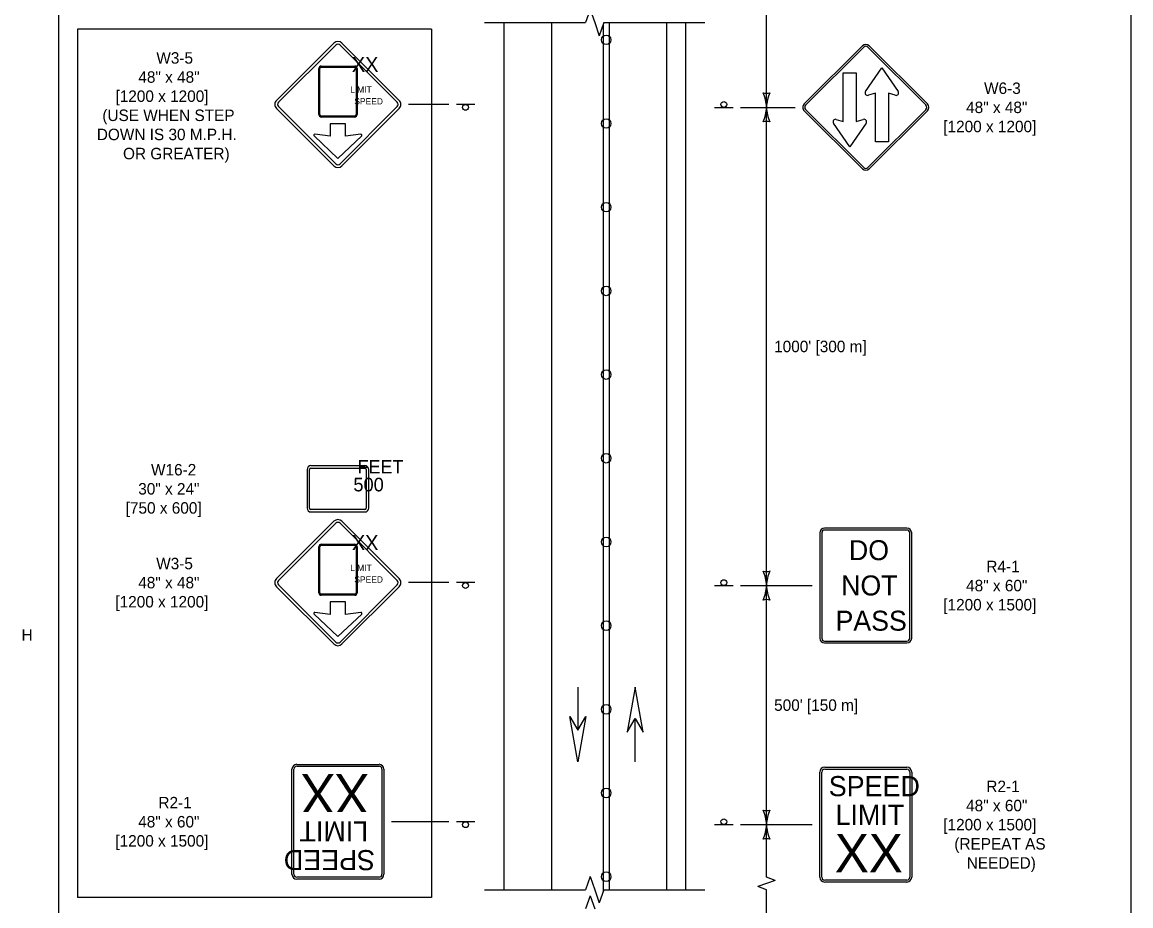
# Model space of a CAD drawing. Extents: x 49991.4 to 50021, y 49987.6 to 50011.4.
# Drawn here: x 50010.96 to 50016.75, y 49990.69 to 49995.31 of the extents above; entities that cross this region are included whole.
import ezdxf

# ---------------------------------------------------------------- set-up
doc = ezdxf.new("R2010")
doc.units = 0
for name, color, linetype in [('Level 1', 7, 'Continuous'), ('Level 2', 7, 'Continuous'), ('Level 3', 7, 'Continuous'), ('Level 6', 7, 'Continuous')]:
    doc.layers.add(name, color=color, linetype=linetype)

msp = doc.modelspace()

# ---------------------------------------------------------------- linework, layer by layer
at = {"layer": 'Level 1'}
for p, q in [((50013.4728, 49995.3125), (50013.4728, 49990.779)), ((50013.7228, 49995.3125), (50013.7228, 49990.779)), ((50013.9928, 49995.3023), (50013.9928, 49990.7689)), ((50014.0228, 49995.3125), (50014.0228, 49990.779)), ((50014.3228, 49995.3125), (50014.3228, 49990.779)), ((50014.4228, 49995.3125), (50014.4228, 49990.779)), ((50012.5844, 49995.2049), (50012.2851, 49994.9056)), ((50012.9264, 49994.9056), (50012.6271, 49995.2049)), ((50012.5945, 49995.1948), (50012.2952, 49994.8955)), ((50012.9163, 49994.8955), (50012.617, 49995.1948)), ((50015.0432, 49994.8868), (50015.3472, 49995.1908)), ((50015.0504, 49994.8798), (50015.3544, 49995.1838)), ((50015.3756, 49995.1838), (50015.6796, 49994.8798)), ((50015.3826, 49995.1908), (50015.6868, 49994.8868)), ((50012.5189, 49995.0848), (50012.6936, 49995.0848)), ((50012.5064, 49994.831), (50012.5064, 49995.0723)), ((50012.5116, 49994.831), (50012.5116, 49995.0723)), ((50012.5189, 49995.0796), (50012.6936, 49995.0796)), ((50012.7009, 49995.0723), (50012.7009, 49994.831)), ((50012.7061, 49995.0723), (50012.7061, 49994.831)), ((50015.2472, 49994.7942), (50015.2472, 49995.0498)), ((50015.2472, 49995.0498), (50015.3152, 49995.0498)), ((50015.3152, 49995.0498), (50015.3152, 49994.7942)), ((50015.3636, 49994.9518), (50015.4488, 49995.0754)), ((50015.4488, 49995.0754), (50015.5338, 49994.9518)), ((50015.4148, 49994.9438), (50015.3784, 49994.9322)), ((50015.4148, 49994.6884), (50015.4148, 49994.9438)), ((50015.5192, 49994.9322), (50015.4828, 49994.9438)), ((50015.4828, 49994.9438), (50015.4828, 49994.6884)), ((50012.2851, 49994.8629), (50012.5844, 49994.5636)), ((50012.2952, 49994.873), (50012.5945, 49994.5737)), ((50012.617, 49994.5737), (50012.9163, 49994.873)), ((50012.6271, 49994.5636), (50012.9264, 49994.8629)), ((50013.3208, 49994.8842), (50013.2248, 49994.8842)), ((50014.5748, 49994.869), (50014.6708, 49994.869)), ((50015.3472, 49994.5474), (50015.0432, 49994.8514)), ((50015.3544, 49994.5544), (50015.0504, 49994.8586)), ((50015.6796, 49994.8586), (50015.3756, 49994.5544)), ((50015.6868, 49994.8514), (50015.3826, 49994.5474)), ((50012.6936, 49994.8237), (50012.5189, 49994.8237)), ((50012.6936, 49994.8185), (50012.5189, 49994.8185)), ((50012.6063, 49994.8185), (50012.6063, 49994.8185)), ((50015.2108, 49994.8062), (50015.2472, 49994.7942)), ((50015.3152, 49994.7942), (50015.3516, 49994.8062)), ((50012.6461, 49994.7834), (50012.5654, 49994.7834)), ((50012.5654, 49994.7834), (50012.5654, 49994.7179)), ((50012.6461, 49994.7179), (50012.6461, 49994.7834)), ((50015.2812, 49994.6628), (50015.196, 49994.7866)), ((50015.3664, 49994.7866), (50015.2812, 49994.6628)), ((50012.4813, 49994.7193), (50012.6057, 49994.602)), ((50012.5654, 49994.7179), (50012.4854, 49994.728)), ((50012.6057, 49994.602), (50012.7302, 49994.7193)), ((50012.7261, 49994.728), (50012.6461, 49994.7179)), ((50015.4828, 49994.6884), (50015.4148, 49994.6884)), ((50012.617, 49994.5737), (50012.617, 49994.5737)), ((50012.6271, 49994.5636), (50012.6271, 49994.5636)), ((50012.4445, 49992.9756), (50012.4445, 49992.7739)), ((50012.4579, 49992.7739), (50012.4579, 49992.9756)), ((50012.7469, 49992.9957), (50012.4646, 49992.9957)), ((50012.4646, 49992.9823), (50012.7469, 49992.9823)), ((50012.7536, 49992.9756), (50012.7536, 49992.7739)), ((50012.767, 49992.7739), (50012.767, 49992.9756)), ((50012.7469, 49992.7672), (50012.4646, 49992.7672)), ((50012.4646, 49992.7538), (50012.7469, 49992.7538)), ((50012.5844, 49992.7049), (50012.2851, 49992.4056)), ((50012.5945, 49992.6948), (50012.2952, 49992.3955)), ((50012.9163, 49992.3955), (50012.617, 49992.6948)), ((50012.9264, 49992.4056), (50012.6271, 49992.7049)), ((50015.5799, 49992.6691), (50015.1499, 49992.6691)), ((50015.5799, 49992.6591), (50015.1499, 49992.6591)), ((50015.1249, 49992.6439), (50015.1249, 49992.0939)), ((50015.1349, 49992.6439), (50015.1349, 49992.0939)), ((50015.5949, 49992.0939), (50015.5949, 49992.6439)), ((50015.6049, 49992.0939), (50015.6049, 49992.6439)), ((50012.5064, 49992.331), (50012.5064, 49992.5723)), ((50012.5116, 49992.331), (50012.5116, 49992.5723)), ((50012.5189, 49992.5848), (50012.6936, 49992.5848)), ((50012.5189, 49992.5796), (50012.6936, 49992.5796)), ((50012.7009, 49992.5723), (50012.7009, 49992.331)), ((50012.7061, 49992.5723), (50012.7061, 49992.331)), ((50012.2851, 49992.3629), (50012.5844, 49992.0636)), ((50012.2952, 49992.373), (50012.5945, 49992.0737)), ((50012.617, 49992.0737), (50012.9163, 49992.373)), ((50012.6271, 49992.0636), (50012.9264, 49992.3629)), ((50013.3208, 49992.3842), (50013.2248, 49992.3842)), ((50014.5748, 49992.369), (50014.6708, 49992.369)), ((50012.6936, 49992.3237), (50012.5189, 49992.3237)), ((50012.6936, 49992.3185), (50012.5189, 49992.3185)), ((50012.6063, 49992.3185), (50012.6063, 49992.3185)), ((50012.6461, 49992.2834), (50012.5654, 49992.2834)), ((50012.5654, 49992.2834), (50012.5654, 49992.2179)), ((50012.6461, 49992.2179), (50012.6461, 49992.2834)), ((50012.4813, 49992.2193), (50012.6057, 49992.102)), ((50012.5654, 49992.2179), (50012.4854, 49992.228)), ((50012.6057, 49992.102), (50012.7302, 49992.2193)), ((50012.7261, 49992.228), (50012.6461, 49992.2179)), ((50012.617, 49992.0737), (50012.617, 49992.0737)), ((50015.1499, 49992.0791), (50015.5799, 49992.0791)), ((50015.1499, 49992.0691), (50015.5799, 49992.0691)), ((50012.6271, 49992.0636), (50012.6271, 49992.0636)), ((50013.8595, 49991.8382), (50013.8595, 49991.6124)), ((50013.8597, 49991.8382), (50013.8597, 49991.6124)), ((50014.1594, 49991.4482), (50014.1594, 49991.674)), ((50014.1596, 49991.4482), (50014.1596, 49991.674)), ((50012.3907, 49991.4343), (50012.8207, 49991.4343)), ((50012.3657, 49990.8593), (50012.3657, 49991.4093)), ((50012.3757, 49990.8593), (50012.3757, 49991.4093)), ((50012.3907, 49991.4243), (50012.8207, 49991.4243)), ((50012.8357, 49991.4093), (50012.8357, 49990.8593)), ((50012.8457, 49991.4093), (50012.8457, 49990.8593)), ((50015.1249, 49990.844), (50015.1249, 49991.394)), ((50015.1349, 49990.844), (50015.1349, 49991.394)), ((50015.1499, 49991.419), (50015.5799, 49991.419)), ((50015.1499, 49991.409), (50015.5799, 49991.409)), ((50015.5949, 49991.394), (50015.5949, 49990.844)), ((50015.6049, 49991.394), (50015.6049, 49990.844)), ((50013.3209, 49991.1343), (50013.2249, 49991.1343)), ((50014.5748, 49991.119), (50014.6708, 49991.119)), ((50012.8207, 49990.8443), (50012.3907, 49990.8443)), ((50012.8207, 49990.8343), (50012.3907, 49990.8343)), ((50015.5799, 49990.829), (50015.1499, 49990.829)), ((50015.5799, 49990.819), (50015.1499, 49990.819))]:
    msp.add_line(p, q, dxfattribs=at)
for points in [[(49999.3835, 49998.9992), (50016.7501, 49998.9992), (50016.7501, 49987.7988), (49999.3835, 49987.7988)], [(50014.2014, 49991.6018), (50014.1596, 49991.8382), (50014.1178, 49991.6018), (50014.1596, 49991.6738)], [(50013.9015, 49991.6846), (50013.8597, 49991.4482), (50013.8179, 49991.6846), (50013.8597, 49991.6126)]]:
    msp.add_lwpolyline(points, close=True, dxfattribs=at)
for centre, radius in [((50014.0079, 49995.222), 0.025), ((50013.2728, 49994.869), 0.0152), ((50014.6229, 49994.8842), 0.0152), ((50014.0079, 49994.7845), 0.025), ((50014.0079, 49994.347), 0.025), ((50014.0079, 49993.9095), 0.025), ((50014.0079, 49993.472), 0.025), ((50014.0079, 49993.0345), 0.025), ((50014.0079, 49992.597), 0.025), ((50013.2728, 49992.369), 0.0152), ((50014.6228, 49992.3842), 0.0152), ((50014.0079, 49992.1595), 0.025), ((50014.0079, 49991.722), 0.025), ((50014.0079, 49991.2845), 0.025), ((50014.6228, 49991.1342), 0.0152), ((50013.2729, 49991.119), 0.0152), ((50014.0079, 49990.847), 0.025)]:
    msp.add_circle(centre, radius, dxfattribs=at)
for centre, radius, start, end in [((50012.6057, 49995.1835), 0.0302, 45.00007, 134.99993), ((50012.6057, 49995.1835), 0.016, 45.00007, 134.99993), ((50015.3649, 49995.1731), 0.025, 45, 135), ((50015.3649, 49995.1731), 0.015, 45, 135), ((50012.5189, 49995.0723), 0.0125, 90, 180), ((50012.6936, 49995.0723), 0.0125, 360, 90), ((50012.5189, 49995.0723), 0.00728, 90, 180), ((50012.6936, 49995.0723), 0.00728, 360, 90), ((50015.3742, 49994.9443), 0.0129, 145.58495, 216.71634), ((50015.3742, 49994.9443), 0.0129, 216.71939, 287.95818), ((50015.5231, 49994.9443), 0.0129, 252.04182, 323.27756), ((50015.5231, 49994.9443), 0.0129, 323.28061, 34.51941), ((50012.3064, 49994.8842), 0.0302, 134.99993, 225.00008), ((50012.3064, 49994.8842), 0.016, 134.99993, 225.00007), ((50012.905, 49994.8842), 0.016, 314.99993, 45.00008), ((50012.905, 49994.8842), 0.0302, 314.99993, 45.00008), ((50015.0608, 49994.869), 0.025, 134.99976, 225), ((50015.0608, 49994.869), 0.015, 134.99976, 225), ((50015.6689, 49994.869), 0.015, 315, 45), ((50015.6689, 49994.869), 0.025, 315, 45), ((50012.5189, 49994.831), 0.0125, 180, 270), ((50012.5189, 49994.831), 0.00728, 180, 270), ((50012.6936, 49994.831), 0.00728, 270, 360), ((50012.6936, 49994.831), 0.0125, 270, 360), ((50015.2067, 49994.7937), 0.0129, 143.28061, 214.51941), ((50015.2067, 49994.7937), 0.0129, 72.04182, 143.27756), ((50015.3555, 49994.7937), 0.0129, 36.71939, 107.95818), ((50015.3555, 49994.7937), 0.0129, 325.58495, 36.71634), ((50012.4849, 49994.7229), 0.00509, 84.38259, 225.16491), ((50012.7266, 49994.7229), 0.00508, 314.62874, 95.82947), ((50012.6057, 49994.5849), 0.0302, 225.00007, 314.99993), ((50012.6057, 49994.5849), 0.016, 225.00007, 314.99993), ((50015.3649, 49994.565), 0.025, 225.00043, 315), ((50015.3649, 49994.565), 0.015, 225.00043, 315), ((50012.4646, 49992.9756), 0.0202, 90, 180), ((50012.4646, 49992.9756), 0.00672, 90, 180), ((50012.7469, 49992.9756), 0.0202, 360, 90), ((50012.7469, 49992.9756), 0.00672, 360, 90), ((50012.4646, 49992.7739), 0.0202, 180, 270), ((50012.4646, 49992.7739), 0.00672, 180, 270), ((50012.7469, 49992.7739), 0.00672, 270, 360), ((50012.7469, 49992.7739), 0.0202, 270, 360), ((50012.6057, 49992.6835), 0.0302, 45.00007, 134.99993), ((50012.6057, 49992.6835), 0.016, 45.00007, 134.99993), ((50015.1498, 49992.644), 0.025, 90, 180), ((50015.1498, 49992.644), 0.015, 90, 180), ((50015.5798, 49992.644), 0.025, 0, 90), ((50015.5798, 49992.644), 0.015, 0, 90), ((50012.5189, 49992.5723), 0.0125, 90, 180), ((50012.5189, 49992.5723), 0.00728, 90, 180), ((50012.6936, 49992.5723), 0.0125, 360, 90), ((50012.6936, 49992.5723), 0.00728, 360, 90), ((50012.3064, 49992.3842), 0.0302, 134.99993, 225.00008), ((50012.3064, 49992.3842), 0.016, 134.99993, 225.00007), ((50012.905, 49992.3842), 0.016, 314.99993, 45.00008), ((50012.905, 49992.3842), 0.0302, 314.99993, 45.00008), ((50012.5189, 49992.331), 0.0125, 180, 270), ((50012.5189, 49992.331), 0.00728, 180, 270), ((50012.6936, 49992.331), 0.00728, 270, 360), ((50012.6936, 49992.331), 0.0125, 270, 360), ((50012.4849, 49992.2229), 0.00509, 84.38259, 225.16491), ((50012.7266, 49992.2229), 0.00508, 314.62874, 95.82947), ((50012.6057, 49992.0849), 0.016, 225.00007, 314.99993), ((50015.1498, 49992.094), 0.025, 180, 270), ((50015.1498, 49992.094), 0.015, 180, 270), ((50015.5798, 49992.094), 0.025, 270, 360), ((50015.5798, 49992.094), 0.015, 270, 360), ((50012.6057, 49992.0849), 0.0302, 225.00007, 314.99993), ((50012.3907, 49991.4094), 0.025, 90, 180), ((50012.8207, 49991.4094), 0.025, 0, 90), ((50012.3907, 49991.4094), 0.015, 90, 180), ((50012.8207, 49991.4094), 0.015, 0, 90), ((50015.1498, 49991.3941), 0.025, 90, 180), ((50015.1498, 49991.3941), 0.015, 90, 180), ((50015.5798, 49991.3941), 0.025, 0, 90), ((50015.5798, 49991.3941), 0.015, 0, 90), ((50012.3907, 49990.8594), 0.025, 180, 270), ((50012.3907, 49990.8594), 0.015, 180, 270), ((50012.8207, 49990.8594), 0.025, 270, 0), ((50012.8207, 49990.8594), 0.015, 270, 0), ((50015.1498, 49990.8441), 0.025, 180, 270), ((50015.1498, 49990.8441), 0.015, 180, 270), ((50015.5798, 49990.8441), 0.025, 270, 0), ((50015.5798, 49990.8441), 0.015, 270, 0)]:
    msp.add_arc(centre, radius, start, end, dxfattribs=at)
at = {"layer": 'Level 2'}
for p, q in [((50013.0948, 49995.2771), (50011.2455, 49995.2771)), ((50011.2455, 49995.2771), (50011.2455, 49990.739)), ((50013.0948, 49995.2771), (50013.0948, 49990.739)), ((50013.0948, 49990.739), (50011.2455, 49990.739))]:
    msp.add_line(p, q, dxfattribs=at)
at = {"layer": 'Level 3'}
for p, q in [((50011.1455, 49998.9992), (50011.1455, 49987.7988)), ((50014.8458, 49994.869), (50014.8458, 49995.4125)), ((50013.1848, 49994.8842), (50012.9753, 49994.8842)), ((50014.7108, 49994.869), (50014.9958, 49994.869)), ((50014.8458, 49992.369), (50014.8458, 49994.869)), ((50013.1848, 49992.3842), (50012.9753, 49992.3842)), ((50014.7108, 49992.369), (50015.0849, 49992.369)), ((50014.8458, 49991.119), (50014.8458, 49992.369)), ((50013.1849, 49991.1343), (50012.8857, 49991.1343)), ((50014.7108, 49991.119), (50015.0849, 49991.119)), ((50014.8458, 49990.8438), (50014.8458, 49991.119)), ((50014.8458, 49990.8114), (50014.8001, 49990.7952)), ((50014.8458, 49990.779), (50014.8001, 49990.7952)), ((50014.8915, 49990.8276), (50014.8458, 49990.8438)), ((50014.8915, 49990.8276), (50014.8458, 49990.8114)), ((50014.8458, 49990.069), (50014.8458, 49990.779))]:
    msp.add_line(p, q, dxfattribs=at)
for centre, radius, start, end in [((50014.8458, 49994.9972), 0.0548, 252.13882, 287.86118), ((50014.6131, 49994.8575), 0.233, 2.82731, 22.07716), ((50015.0679, 49994.8599), 0.2223, 157.45601, 177.63952), ((50014.6237, 49994.8782), 0.2223, 337.45601, 357.63952), ((50015.0785, 49994.8805), 0.233, 182.82731, 202.07716), ((50014.8458, 49994.7408), 0.0548, 72.13882, 107.86118), ((50014.8458, 49992.4972), 0.0548, 252.13882, 287.86118), ((50014.6131, 49992.3575), 0.233, 2.82731, 22.07716), ((50015.0679, 49992.3599), 0.2223, 157.45601, 177.63952), ((50014.6237, 49992.3782), 0.2223, 337.45601, 357.63952), ((50015.0785, 49992.3805), 0.233, 182.82731, 202.07716), ((50014.8458, 49992.2408), 0.0548, 72.13882, 107.86118), ((50014.8458, 49991.2472), 0.0548, 252.13882, 287.86118), ((50014.6131, 49991.1075), 0.233, 2.82731, 22.07716), ((50015.0679, 49991.1099), 0.2223, 157.45601, 177.63952), ((50014.6237, 49991.1282), 0.2223, 337.45601, 357.63952), ((50015.0785, 49991.1305), 0.233, 182.82731, 202.07716), ((50014.8458, 49990.9908), 0.0548, 72.13882, 107.86118)]:
    msp.add_arc(centre, radius, start, end, dxfattribs=at)
at = {"layer": 'Level 6'}
for p, q in [((50013.9236, 49995.3809), (50013.8992, 49995.3125)), ((50013.9236, 49995.3809), (50013.9478, 49995.3125)), ((50013.3728, 49995.3125), (50013.8992, 49995.3125)), ((50013.9478, 49995.3125), (50013.972, 49995.2437)), ((50013.9964, 49995.3125), (50013.972, 49995.2437)), ((50013.9964, 49995.3125), (50014.5228, 49995.3125)), ((50013.9236, 49990.8474), (50013.8992, 49990.779)), ((50013.9236, 49990.8474), (50013.9478, 49990.779)), ((50013.3728, 49990.779), (50013.8992, 49990.779)), ((50013.9236, 49990.7474), (50013.8992, 49990.679)), ((50013.9236, 49990.7474), (50013.9478, 49990.679)), ((50013.9478, 49990.779), (50013.972, 49990.7102)), ((50013.9964, 49990.779), (50013.972, 49990.7102)), ((50013.9964, 49990.779), (50014.5228, 49990.779))]:
    msp.add_line(p, q, dxfattribs=at)

# ---------------------------------------------------------------- texts
at = {"layer": 'Level 1'}
for s, height, rotation, p in [('XX', 0.07775, 360, (50012.6788, 49995.0547)), ('LIMIT', 0.03301, 360, (50012.6697, 49994.9452)), ('SPEED', 0.03301, 360, (50012.6916, 49994.8842)), ('FEET', 0.06989, 360, (50012.709, 49992.9554)), ('XX', 0.07775, 360, (50012.6788, 49992.5547)), ('LIMIT', 0.03301, 360, (50012.6697, 49992.4452)), ('SPEED', 0.03301, 360, (50012.6916, 49992.3842)), ('XX', 0.19892, 180, (50012.7673, 49991.3837)), ('SPEED', 0.10512, 360, (50015.1711, 49991.2679)), ('LIMIT', 0.10512, 360, (50015.2065, 49991.1178)), ('LIMIT', 0.10512, 180, (50012.7641, 49991.1365)), ('XX', 0.1989, 360, (50015.2033, 49990.8705)), ('SPEED', 0.10512, 180, (50012.7996, 49990.9863))]:
    msp.add_text(s, height=height, rotation=rotation, dxfattribs=at).set_placement(p)
for s, height, p in [('500', 0.07124, (50012.6866, 49992.8613)), ('DO', 0.1044, (50015.2768, 49992.5018)), ('NOT', 0.1044, (50015.2361, 49992.3174)), ('PASS', 0.1044, (50015.2067, 49992.133))]:
    msp.add_text(s, height=height, dxfattribs=at).set_placement(p)
at = {"layer": 'Level 2'}
for s, height, p in [('W3-5', 0.06, (50011.6568, 49995.0975)), ('48" x 48"', 0.06, (50011.5628, 49994.9975)), ('W6-3', 0.06, (50015.9831, 49994.939)), ('[1200 x 1200]', 0.06, (50011.4433, 49994.8975)), ('(USE WHEN STEP', 0.06, (50011.3746, 49994.7975)), ('48" x 48"', 0.06, (50015.8893, 49994.839)), ('[1200 x 1200]', 0.06, (50015.7699, 49994.739)), ('DOWN IS 30 M.P.H.', 0.06, (50011.3457, 49994.6975)), ('OR GREATER)', 0.06, (50011.4826, 49994.5975)), ("1000' [300 m]", 0.06, (50014.8858, 49993.589)), ('W16-2', 0.05999, (50011.629, 49992.9446)), ('30" x 24"', 0.05999, (50011.5622, 49992.8448)), ('[750 x 600]', 0.059993, (50011.4966, 49992.7449)), ('W3-5', 0.05999, (50011.6562, 49992.4541)), ('R4-1', 0.06, (50015.9949, 49992.4389)), ('48" x 48"', 0.05999, (50011.5622, 49992.3543)), ('48" x 60"', 0.06, (50015.8893, 49992.3389)), ('[1200 x 1200]', 0.059993, (50011.4427, 49992.2544)), ('[1200 x 1500]', 0.06, (50015.7699, 49992.2389)), ('H', 0.06, (50010.9522, 49992.0804)), ("500' [150 m]", 0.06, (50014.8858, 49991.714)), ('R2-1', 0.06, (50015.9949, 49991.289)), ('R2-1', 0.06, (50011.6677, 49991.2043)), ('48" x 60"', 0.06, (50015.8893, 49991.189)), ('48" x 60"', 0.06, (50011.5621, 49991.1043)), ('[1200 x 1500]', 0.06, (50015.7699, 49991.089)), ('[1200 x 1500]', 0.06, (50011.4427, 49991.0043)), ('(REPEAT AS', 0.06, (50015.8277, 49990.989)), ('NEEDED)', 0.06, (50015.8924, 49990.889))]:
    msp.add_text(s, height=height, dxfattribs=at).set_placement(p)

doc.saveas('drawing.dxf')
